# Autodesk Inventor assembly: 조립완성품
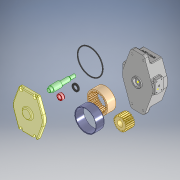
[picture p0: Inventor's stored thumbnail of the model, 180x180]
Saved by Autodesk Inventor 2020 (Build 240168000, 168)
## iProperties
Created: 2023-11
Part Number: 조립완성품
Document SubType Name: Assembly
Designer: CAD16
Author: CAD16
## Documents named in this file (10)
- C:\Users\CAD16\Desktop\731106V1006\조립완성품.iam
- C:\Users\CAD16\Desktop\731106V1006\본체.ipt
- C:\Users\CAD16\Desktop\731106V1006\DU 부시.ipt
- C:\Users\CAD16\Desktop\731106V1006\O링 G90.ipt
- C:\Users\CAD16\Desktop\731106V1006\내접기어.ipt
- C:\Users\CAD16\Desktop\731106V1006\스퍼기어.ipt
- C:\Users\CAD16\Desktop\731106V1006\오일 실 14 25 4.ipt
- C:\Users\CAD16\Desktop\731106V1006\오일레스 부시.ipt
- C:\Users\CAD16\Desktop\731106V1006\축.ipt
- C:\Users\CAD16\Desktop\731106V1006\커버.ipt
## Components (2 placed, 2 different names)
1. DU 부시:1
2. O링 G90:1
